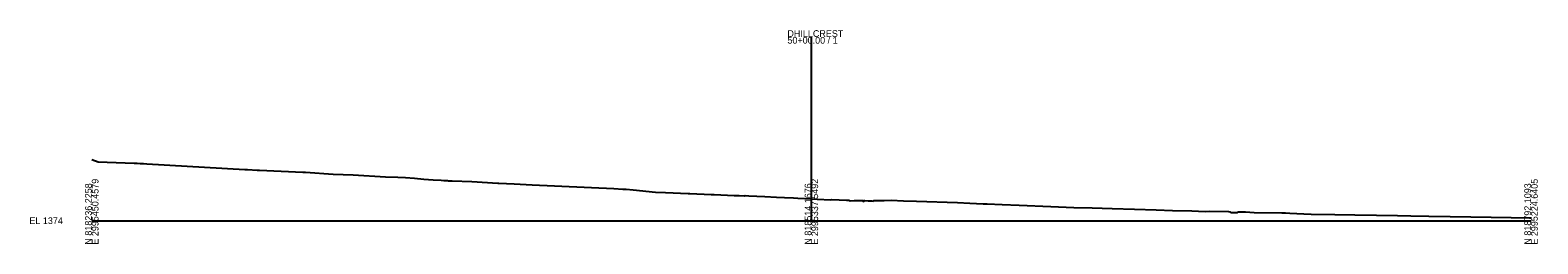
# Model space of a CAD drawing. Extents: x -26 to 603, y -10 to 2564.
# Drawn here: x -26 to 603, y -10 to 80 of the extents above; entities that cross this region are included whole.
import ezdxf

# ---------------------------------------------------------------- set-up
doc = ezdxf.new("R2010")
doc.units = 0
doc.layers.add('DESIGN - SHEET - Light Grid', color=7, linetype='Continuous')
doc.layers.add('SURVEY - GROUND - Top of Ground', color=7, linetype='Continuous')

msp = doc.modelspace()

# ---------------------------------------------------------------- linework, layer by layer
at = {"layer": 'DESIGN - SHEET - Light Grid'}
for p, q in [((300, 0), (300, 76.72)), ((0, 0), (300, 0)), ((300, 0), (600, 0))]:
    msp.add_line(p, q, dxfattribs=at)
at = {"layer": 'SURVEY - GROUND - Top of Ground'}
msp.add_lwpolyline([(0, 25.57), (2.62, 24.61), (17.63, 24.05), (18.88, 23.98), (20.18, 23.91), (21.56, 23.83), (23, 23.75), (63.78, 21.38), (64.85, 21.32), (68.92, 21.09), (69.94, 21.03), (87.96, 20.28), (89.03, 20.21), (100.69, 19.38), (109.01, 19.1), (122.38, 18.35), (127.55, 18.14), (130.79, 18), (134.54, 17.73), (138.4, 17.39), (142.33, 17.04), (145.59, 16.85), (146.79, 16.8), (148.3, 16.71), (148.64, 16.68), (150.22, 16.58), (158.45, 16.35), (169.21, 15.62), (169.65, 15.7), (176.11, 15.43), (183.58, 14.92), (217.63, 13.45), (221.42, 13.21), (221.83, 13.17), (222.71, 13.09), (225.68, 12.81), (234.94, 11.97), (239.19, 11.79), (248.6, 11.38), (249.33, 11.34), (258.21, 10.95), (259.48, 10.89), (267.8, 10.52), (269.02, 10.46), (269.85, 10.45), (271.97, 10.31), (272.35, 10.48), (273.98, 10.36), (280.57, 10.05), (285.41, 9.81), (288.8, 9.64), (292.48, 9.48), (294.33, 9.4), (300, 9.12), (302.47, 9), (307.91, 8.74), (308.56, 8.8), (314.63, 8.5), (315.57, 8.5), (316.09, 8.35), (317.76, 8.49), (321.51, 8.39), (321.63, 8.07), (322.29, 8.49), (322.29, 8.49), (323.61, 8.33), (324.6, 8.25), (325.18, 8.23), (325.8, 8.19), (326.12, 8.38), (327.12, 8.48), (330.38, 8.46), (333.31, 8.52), (338.37, 8.32), (343.84, 8.11), (360.93, 7.53), (366.02, 7.32), (371.57, 7.1), (373.3, 7.03), (379.58, 6.76), (386.59, 6.47), (399.78, 5.96), (406.27, 5.68), (409.42, 5.54), (417.03, 5.3), (425.41, 5.03), (434.69, 4.74), (443.68, 4.52), (450.47, 4.28), (458.65, 4.05), (464.21, 3.89), (465.96, 3.93), (473.89, 3.87), (474.4, 3.76), (474.8, 3.47), (477.61, 3.41), (478.06, 3.72), (479.59, 3.7), (480.96, 3.68), (484.57, 3.41), (496.07, 3.24), (496.42, 3.24), (496.73, 3.23), (497.67, 3.23), (499.51, 3.13), (505.31, 2.81), (508.33, 2.76), (518.2, 2.58), (526.49, 2.42), (535.58, 2.27), (544.4, 2.12), (549.87, 2.05), (557.38, 1.92), (566.3, 1.78), (574.95, 1.63), (583.33, 1.5), (591.7, 1.36), (600, 1.21)], dxfattribs=at)

# ---------------------------------------------------------------- texts
at = {"layer": 'DESIGN - SHEET - Light Grid'}
for s, p in [('50+00.00 / 1', (290, 73.92)), ('DHILLCREST', (290, 76.72)), ('EL 1374', (-26, -1.4))]:
    msp.add_text(s, height=2.8, dxfattribs=at).set_placement(p)
for s, p in [('N 818236.2258', (0, -10)), ('E 2995450.4579', (2.8, -10)), ('N 818514.1676', (300, -10)), ('E 2995337.5492', (302.8, -10)), ('N 818792.1093', (600, -10)), ('E 2995224.6405', (602.8, -10))]:
    msp.add_text(s, height=2.8, rotation=90, dxfattribs=at).set_placement(p)

doc.saveas('drawing.dxf')
